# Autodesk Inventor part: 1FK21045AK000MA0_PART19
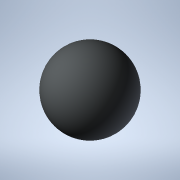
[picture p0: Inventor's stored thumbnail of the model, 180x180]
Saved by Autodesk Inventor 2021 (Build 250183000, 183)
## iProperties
Created: 2025-04
Part Number: 1FK21045AK000MA0_PART19
Material: Generic
Catalog Web Link: www.3dfindit.com
Description: -Servo synchronous motor
Document SubType Name: Modeling
Designer: psAdmin
Mass: 0.137258 g
Surface Area: 1.2868 cm^2
Volume: 0.137258 cm^3
Density: 1 g/cm^3
Appearance: PSOLRGB-212-217-219
Category: PARTsolutions
Title: 1FK21045AK000MA0_PART19
Author: Cadenas PARTsolutions
Comments: Servo synchronous motor
Sending System: PARTsolutions
Preprocessor: ST-DEVELOPER v19.3
PSOL_IDENT_0: {$CADENAS_DATA/23d-libs/siemens_ag/_cat_/3d/2f/1fk21045ak000ma0.prj},216 {VTYP=3D},{NB=1FK21045AK000
PSOL_IDENT_1: MA0_PART19},{LINA=1FK21045AK000MA0_PART19},{NN=1FK21045AK000MA0_PART19},{NOPRJ=TRUE},{DATE=19.08.202
PSOL_IDENT_2: 5 14:00:34},{GEOMDATE=30.07.2025 02:01:24},{VERSION=},{LINEID=10},{WBVAR=},{WBNUMERIC=}  {NB=1FK2104
PSOL_IDENT_3: 5AK000MA0_PART19},{LINA=1FK21045AK000MA0_PART19},{KT=DUMMY},{PREVIEW=../../../_pool_/a9/69/p_d211_xx
PSOL_IDENT_4: _00818j.png},{DESCSHORT=SIMOTICS S-1FK2 HD, SINAMICS S210 3AC 400V-480V, 1.7 Nm, 6000 rpm},{DESCLONG=
PSOL_IDENT_5: SIMOTICS S-1FK2 HD servo motor M0=2.4 Nm; PN = 1.07 kW at nN=6000 rpm (380-480 V); PN = 0.75 kW at n
PSOL_IDENT_6: N=3000 rpm (200-240 V); degree of protection IP64; cylindrical shaft D19x40mm; absolute encoder 22-b
PSOL_IDENT_7: it + 12-bit multiturn (encoder AM22DQC); with OCC interface; plug size M17, rotatable; SIMOTICS S-1F
PSOL_IDENT_8: K2 servomotorfor a wide range of uses in industrial environments. SIMOTICS S‑1FK2 servomotors are co
PSOL_IDENT_9: mpact synchronous motors with a high dynamic performance that set themselves apart as a result of th
PSOL_IDENT_10: eir high power density, degree of protection and overload capability. The motors are available in tw
PSOL_IDENT_11: o variants: as High Dynamic variant (highest dynamic performance as a result of the low intrinsic mo
PSOL_IDENT_12: ment of inertia for applications demanding a high dynamic performance with low moved masses) - and a
PSOL_IDENT_13: s Compact variant (precise and stable closed-loop control for medium up to large moved masses as a r
PSOL_IDENT_14: esult of a medium intrinsic moment of inertia). SIMOTICSS‑1FK2 servomotors fully exploit their stren
PSOL_IDENT_15: gths in a system with the SINAMICSS210 frequency converter and simple connection using the one cable
PSOL_IDENT_16: connection (OCC). Advantages include the short control and positioning times, fast and precise corr
PSOL_IDENT_17: ection of disturbing quantities as well as stable control with a high dynamic performance. The servo
PSOL_IDENT_18: motors can be configured to address a wide range of requirements. For example with and without hold
PSOL_IDENT_19: ing brake, IP64 or IP65 degree of protection, singleturn or multiturn absolute encoders - to name ju
PSOL_IDENT_20: st a few. Further, the servomotors are available in different shaft heights extending from 20 to 100
PSOL_IDENT_21: . A shaft sealing ring is available to achieve an IP65 degree of protection and for subsequent mount
PSOL_IDENT_22: ing at the motor or as spare part. SIMOTICS - the optimum motor for each and every motion control ap
PSOL_IDENT_23: plication.},{INTNO=804766789342},{SUPPLIERALTNO=1FK2104-5AK00-0MA0},{MANUID=1FK21045AK000MA0},{MANUN
PSOL_IDENT_24: AME=Siemens},{MANUTYPEDESC=Synchronous motor 1FK2-HD 2,39 Nm},{AAU732=SIMOTICS},{AAO057=S-1FK2},{AAU
PSOL_IDENT_25: 734=SIMOTICS S-1FK2 HD servo motor M0=2.4 Nm; PN = 1.07 kW at nN=6000 rpm (380-480 V); PN = 0.75 kW
PSOL_IDENT_26: at nN=3000 rpm (200-240 V); degree of protection IP64; cylindrical shaft D19x40mm; absolute encoder
PSOL_IDENT_27: 22-bit + 12-bit multiturn (encoder AM22DQC); with OCC interface; plug size M17, rotatable;},{AAW338=
PSOL_IDENT_28: Synchronous motor 1FK2-HD 2,39 Nm},{AAO742=SIMOTICS},{AAO663=4042948691151},{NOCUPEROU=1},{PRICEQUAN
PSOL_IDENT_29: TITY=1},{QUANTITYMIN=1},{QUANTITYINT=1},{CTN=85015100},{COO=DE},{AAO676=1FK2104-5AK00-0MA0},{AAO677=
PSOL_IDENT_30: Siemens AG},{ORDERUNIT=C62},{CONTENTUNIT=C62}
NB: 1FK21045AK000MA0_PART19
NT: Servo synchronous motor
NBSYN: $MANUID._PART19
LINA: 1FK21045AK000MA0_PART19
CATALOG: SIEMENS
PREVIEW: ../../../_pool_/a9/69/p_d211_xx_00818j.png
DESCSHORT: SIMOTICS S-1FK2 HD, SINAMICS S210 3AC 400V-480V, 1.7 Nm, 6000 rpm
DESCLONG: SIMOTICS S-1FK2 HD servo motor M0=2.4 Nm; PN = 1.07 kW at nN=6000 rpm (380-480 V); PN = 0.75 kW at nN=3000 rpm (200-240 V); degree of protection IP64; cylindric
INTNO: 804766789342
SUPPLIERALTNO: 1FK2104-5AK00-0MA0
MANUID: 1FK21045AK000MA0
MANUNAME: Siemens
MANUTYPEDESC: Synchronous motor 1FK2-HD 2,39 Nm
AAU732: SIMOTICS
AAO057: S-1FK2
AAU734: SIMOTICS S-1FK2 HD servo motor M0=2.4 Nm; PN = 1.07 kW at nN=6000 rpm (380-480 V); PN = 0.75 kW at nN=3000 rpm (200-240 V); degree of protection IP64; cylindric
AAW338: Synchronous motor 1FK2-HD 2,39 Nm
AAO742: SIMOTICS
AAO663: 4042948691151.0
NOCUPEROU: 1
PRICEQUANTITY: 1
QUANTITYMIN: 1
QUANTITYINT: 1
CTN: 85015100
COO: DE
ARTICLENO: 1FK21045AK000MA0_PART19
BOMINFO: 1FK21045AK000MA0_PART19
CREATOR: CADENAS GmbH
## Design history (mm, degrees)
feature "2025_04_17_15_39_51_0728"
body "Solid1"
